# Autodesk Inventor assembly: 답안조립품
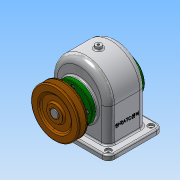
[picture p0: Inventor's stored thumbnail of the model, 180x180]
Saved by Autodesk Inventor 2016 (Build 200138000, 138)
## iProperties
Created: 2018-08
Part Number: 답안조립품
Material: 일반
Document SubType Name: Assembly
Designer: Administrator
Author: Administrator
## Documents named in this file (14)
- C:\Users\Administrator\Desktop\480811v1007\답안조립품.iam
- C:\Users\Administrator\Desktop\480811v1007\본체.ipt
- C:\Users\Administrator\Desktop\480811v1007\베어링 6203.ipt
- C:\Users\Administrator\Desktop\480811v1007\축.ipt
- C:\Users\Administrator\Desktop\480811v1007\키 6x6x22.ipt
- C:\Users\Administrator\Desktop\480811v1007\스퍼기어.ipt
- C:\Users\Administrator\Desktop\480811v1007\앞커버.ipt
- C:\Users\Administrator\Desktop\480811v1007\부시.ipt
- C:\Users\Administrator\Desktop\480811v1007\오일 실 28 40 8.ipt
- C:\Users\Administrator\Desktop\480811v1007\뒤커버.ipt
- C:\Users\Administrator\Desktop\480811v1007\볼트 M4.ipt
- C:\Users\Administrator\Desktop\480811v1007\V-벨트풀리.ipt
- C:\Users\Administrator\Desktop\480811v1007\키 5x5x18.ipt
- C:\Users\Administrator\Desktop\480811v1007\멈춤나사 M4.ipt
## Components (1 placed, 1 different names)
1. V-벨트풀리:1
